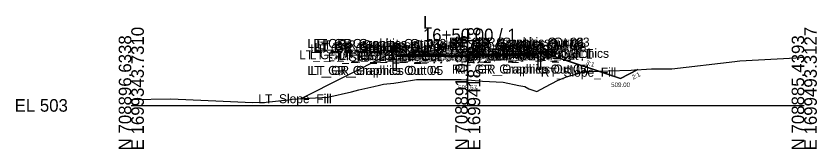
# Model space of a CAD drawing. Extents: x -63 to 1153, y -24 to 9522.
# Drawn here: x -25.7 to 152.8, y 7990.3 to 8019.9 of the extents above; entities that cross this region are included whole.
import ezdxf

# ---------------------------------------------------------------- set-up
doc = ezdxf.new("R2010")
doc.units = 0
for name, color, linetype in [('Default', 7, 'Continuous'), ('Exist Cross Section Cell', 7, 'Continuous'), ('Exist XS Center Line Elevation Label', 7, 'Continuous'), ('Exist XS Ground Line', 7, 'Continuous'), ('Prop CMT DNC', 7, 'Continuous'), ('Prop CMT Guardrail Graphics', 7, 'Continuous'), ('Prop CMT Pvmt Course 1', 7, 'Continuous'), ('Prop CMT Pvmt Course 2', 7, 'Continuous'), ('Prop CMT Pvmt Surface', 7, 'Continuous'), ('Prop CMT Pvmt Surface Overlay', 7, 'Continuous'), ('Prop CMT Pvmt Surface Shoulder', 7, 'Continuous'), ('Prop CMT Shld Paved Course 1', 7, 'Continuous'), ('Prop CMT Shld Paved Course 2', 7, 'Continuous'), ('Prop CMT Slope Grass', 7, 'Continuous'), ('Prop CMT Subgrade Earthwork', 7, 'Continuous'), ('Prop XS Ditch Standard Text', 7, 'Continuous'), ('Prop XS Earthwork Shape', 7, 'Continuous'), ('Prop XS EOT Tick Mark', 7, 'Continuous'), ('Prop XS SE Text', 7, 'Continuous'), ('Prop XS Side Slope Text', 7, 'Continuous')]:
    doc.layers.add(name, color=color, linetype=linetype)

msp = doc.modelspace()

# ---------------------------------------------------------------- linework, layer by layer
at = {"layer": 'Exist Cross Section Cell'}
for p, q in [((75, 8000), (75, 8017.09)), ((0, 8000), (75, 8000)), ((75, 8000), (150, 8000))]:
    msp.add_line(p, q, dxfattribs=at)
at = {"layer": 'Exist XS Ground Line'}
msp.add_lwpolyline([(0, 8001.3), (8.8, 8001.47), (20.45, 8000.98), (27.03, 8000.65), (30.06, 8000.69), (34.91, 8001.22), (35.88, 8001.36), (39.71, 8001.62), (43.79, 8001.8), (49.1, 8002.99), (50.72, 8003.47), (54.04, 8004.24), (55.31, 8004.54), (55.91, 8004.66), (56.23, 8004.7), (58.53, 8004.98), (59.96, 8005.18), (63.61, 8005.76), (68.55, 8005.77), (73.5, 8005.78), (75, 8005.67), (78.32, 8005.42), (82.88, 8005.17), (86.41, 8004.4), (87.72, 8004.22), (88.59, 8003.7), (90.41, 8003.11), (92.34, 8004.17), (95, 8005.51), (96.99, 8006.38), (100.4, 8007.3), (101.59, 8007.52), (106.3, 8007.67), (111.43, 8007.88), (115.95, 8008.14), (120.51, 8008.15), (134.52, 8009.8), (135.08, 8009.84), (135.66, 8009.89), (148.16, 8010.6), (150, 8010.77)], dxfattribs=at)
at = {"layer": 'Prop CMT Guardrail Graphics'}
for points in [[(58.37, 8007.79), (58.37, 8013.79)], [(58.37, 8013.79), (59.71, 8013.79), (59.98, 8013.5)], [(59.98, 8012.92), (59.71, 8012.63), (59.04, 8012.63)], [(59.04, 8012.63), (59.04, 8007.79)], [(59.98, 8013.5), (59.71, 8013.21)], [(59.71, 8013.21), (59.98, 8012.92)], [(91.28, 8014.09), (89.95, 8014.09), (89.68, 8013.8)], [(89.68, 8013.8), (89.95, 8013.51)], [(89.95, 8013.51), (89.68, 8013.22)], [(89.68, 8013.22), (89.95, 8012.93), (90.61, 8012.93)], [(90.61, 8012.93), (90.61, 8008.09)], [(91.28, 8008.09), (91.28, 8014.09)], [(59.04, 8007.79), (58.37, 8007.79)], [(90.61, 8008.09), (91.28, 8008.09)]]:
    msp.add_lwpolyline(points, dxfattribs=at)
at = {"layer": 'Prop CMT Pvmt Course 1'}
for points in [[(75, 8011.45), (65, 8011.35)], [(65, 8011.35), (65, 8011.1)], [(65, 8011.1), (75, 8011.2)], [(75, 8011.45), (85, 8011.55)], [(75, 8011.33), (75, 8011.45)], [(75, 8011.33), (75, 8011.45)], [(75, 8011.2), (75, 8011.33), (75, 8011.33)], [(75, 8011.2), (75, 8011.33), (75, 8011.33)], [(85, 8011.3), (75, 8011.2)], [(85, 8011.55), (85, 8011.3)]]:
    msp.add_lwpolyline(points, dxfattribs=at)
at = {"layer": 'Prop CMT Pvmt Course 2'}
for points in [[(75, 8011.2), (65, 8011.1)], [(65, 8011.1), (65, 8010.85)], [(65, 8010.85), (75, 8010.95)], [(75, 8011.2), (85, 8011.3)], [(75, 8010.95), (75, 8011.2)], [(75, 8010.95), (75, 8011.2)], [(85, 8011.05), (75, 8010.95)], [(85, 8011.3), (85, 8011.05)]]:
    msp.add_lwpolyline(points, dxfattribs=at)
at = {"layer": 'Prop CMT Pvmt Surface'}
for points in [[(75, 8011.45), (65, 8011.35)], [(75, 8011.45), (85, 8011.55)]]:
    msp.add_lwpolyline(points, dxfattribs=at)
at = {"layer": 'Prop CMT Pvmt Surface Overlay'}
for points in [[(75, 8011.45), (65, 8011.35)], [(75, 8011.45), (85, 8011.55)]]:
    msp.add_lwpolyline(points, dxfattribs=at)
at = {"layer": 'Prop CMT Pvmt Surface Shoulder'}
for points in [[(65, 8011.35), (60.16, 8011.31)], [(85, 8011.55), (89.58, 8011.6)]]:
    msp.add_lwpolyline(points, dxfattribs=at)
at = {"layer": 'Prop CMT Shld Paved Course 1'}
for points in [[(65, 8011.35), (60.16, 8011.31), (59.91, 8011.05)], [(59.91, 8011.05), (65, 8011.1)], [(65, 8011.1), (65, 8011.35)], [(85, 8011.55), (89.58, 8011.6), (89.82, 8011.35)], [(85, 8011.3), (85, 8011.55)], [(89.82, 8011.35), (85, 8011.3)]]:
    msp.add_lwpolyline(points, dxfattribs=at)
at = {"layer": 'Prop CMT Shld Paved Course 2'}
for points in [[(59.91, 8011.05), (59.66, 8010.8)], [(59.66, 8010.8), (65, 8010.85)], [(65, 8011.1), (59.91, 8011.05)], [(59.91, 8011.05), (59.91, 8011.05)], [(65, 8010.85), (65, 8011.1)], [(85, 8011.3), (89.82, 8011.35)], [(85, 8011.05), (85, 8011.3)], [(90.07, 8011.1), (85, 8011.05)], [(89.82, 8011.35), (89.82, 8011.35)], [(89.82, 8011.35), (90.07, 8011.1)]]:
    msp.add_lwpolyline(points, dxfattribs=at)
at = {"layer": 'Prop CMT Slope Grass'}
for p, q in [((92.68, 8011.44), (109.01, 8006)), ((109.01, 8006), (112.94, 8007.96))]:
    msp.add_line(p, q, dxfattribs=at)
for points in [[(56.98, 8011.08), (37.79, 8001.49)], [(59.98, 8011.29), (56.98, 8011.08)], [(60.16, 8011.31), (59.98, 8011.29)], [(89.58, 8011.6), (89.68, 8011.59)], [(89.68, 8011.59), (92.68, 8011.44)]]:
    msp.add_lwpolyline(points, dxfattribs=at)
at = {"layer": 'Prop CMT Subgrade Earthwork'}
for points in [[(59.66, 8010.8), (59.22, 8011.24)], [(65, 8010.85), (59.66, 8010.8)], [(75, 8010.95), (65, 8010.85)], [(75, 8010.95), (85, 8011.05)], [(85, 8011.05), (90.07, 8011.1)], [(90.07, 8011.1), (90.52, 8011.55)]]:
    msp.add_lwpolyline(points, dxfattribs=at)
at = {"layer": 'Prop XS Earthwork Shape'}
for points in [[(56.98, 8011.08), (37.79, 8001.49), (39.71, 8001.62), (43.79, 8001.8), (49.1, 8002.99), (50.72, 8003.47), (54.04, 8004.24), (55.31, 8004.54), (55.91, 8004.66), (56.23, 8004.7), (58.53, 8004.98), (59.96, 8005.18), (63.61, 8005.76), (68.55, 8005.77), (73.5, 8005.78), (75, 8005.67), (78.32, 8005.42), (82.88, 8005.17), (86.41, 8004.4), (87.72, 8004.22), (88.59, 8003.7), (90.41, 8003.11), (92.34, 8004.17), (95, 8005.51), (96.99, 8006.38), (100.4, 8007.3), (101.59, 8007.52), (104.21, 8007.6), (92.68, 8011.44), (90.52, 8011.55), (90.07, 8011.1), (85, 8011.05), (75, 8010.95), (65, 8010.85), (59.66, 8010.8), (59.22, 8011.24)], [(106.3, 8007.67), (111.43, 8007.88), (112.94, 8007.96), (109.01, 8006), (104.21, 8007.6)]]:
    msp.add_lwpolyline(points, close=True, dxfattribs=at)
at = {"layer": 'Prop XS EOT Tick Mark'}
for points in [[(85, 8011.55), (85, 8012.55)], [(65, 8011.35), (65, 8012.35)]]:
    msp.add_lwpolyline(points, dxfattribs=at)

# ---------------------------------------------------------------- texts
at = {"layer": 'Default'}
msp.add_text('-', height=0.0001, dxfattribs=at).set_placement((0, 8000))
at = {"layer": 'Exist Cross Section Cell'}
for s, p in [('L', (65, 8017.09)), ('16+50.00 / 1', (65, 8014.29)), ('EL 503', (-26, 7998.6))]:
    msp.add_text(s, height=2.8, dxfattribs=at).set_placement(p)
for s, p in [('E 1699343.7310', (2.8, 7990)), ('E 1699418.5218', (77.8, 7990)), ('E 1699493.3127', (152.8, 7990)), ('N 708896.6338', (0, 7990)), ('N 708891.0366', (75, 7990)), ('N 708885.4393', (150, 7990))]:
    msp.add_text(s, height=2.8, rotation=90, dxfattribs=at).set_placement(p)
at = {"layer": 'Exist XS Center Line Elevation Label'}
msp.add_text('508.67', height=1, dxfattribs=at).set_placement((72.85, 8003.49))
at = {"layer": 'Prop CMT DNC'}
for s, p in [('LT_GR_Graphics Out 03', (39.27, 8012.79)), ('LT_GR_Graphics Out 02', (40.6, 8012.79)), ('LT_GR_Graphics Out 01', (41.44, 8012.5)), ('RT_GR_Graphics Out 02', (70.8, 8013.09)), ('RT_GR_Graphics Out 09', (70.8, 8012.51)), ('RT_GR_Graphics Out 01', (71.09, 8012.8)), ('RT_GR_Graphics Out 03', (72.13, 8013.09)), ('LT_GR_Graphics Out 06', (39.89, 8011.63)), ('LT_GR_Graphics Out 09', (40.6, 8012.21)), ('LT_GR_Graphics Out 07', (40.6, 8011.63)), ('LT_GR_Graphics Out 08', (40.87, 8011.92)), ('LT_TM_OEOT', (55.94, 8011.35)), ('RT_GS_OS_GR_Face_Graphics', (67.09, 8010.59)), ('RT_GR_Graphics Out 08', (70.53, 8012.22)), ('RT_GR_Graphics Out 07', (70.8, 8011.93)), ('RT_Sub_Trench_Out_DLT', (71.04, 8010.55)), ('RT_GR_Graphics Out 06', (71.42, 8011.93)), ('RT_PV1_OEOT', (75.69, 8010.55)), ('RT_TM_OEOT', (75.9, 8011.55)), ('RT_PS1_OEOP', (80.33, 8010.6)), ('LT_GS_OS_GR_Face_Graphics', (37.43, 8010.29)), ('LT_Sub_Trench_Out_DLT', (39.78, 8010.24)), ('LT_Sub_Trench_Out', (43.86, 8009.8)), ('LT_PS2_Shelf_Out', (45.89, 8010.05)), ('LT_GS_OS_CTL', (46.35, 8010.08)), ('LT_PS2_OEOP', (50.15, 8010.05)), ('LT_PS1_OEOP', (50.96, 8010.31)), ('LT_Sub_OEOT', (55.08, 8009.85)), ('LT_PV2_OEOT', (55.17, 8010.1)), ('LT_PV1_OEOT', (55.74, 8010.35)), ('RT_PV1_OEEOP_W', (62.94, 8010.33)), ('LT_PV1_OEEOP_W', (62.98, 8010.33)), ('RT_Sub_OEEOP', (64.17, 8009.95)), ('LT_Sub_OEEOP', (64.21, 8009.95)), ('RT_PV2_OEEOP', (64.26, 8010.2)), ('LT_PV2_OEEOP', (64.31, 8010.2)), ('PV1_PGL_W', (67.58, 8010.33)), ('PV1_PGL', (69.47, 8010.45)), ('RT_Sub_Trench_Out', (74.23, 8010.1)), ('RT_Sub_OEOT', (75.03, 8010.05)), ('RT_PV2_OEOT', (75.13, 8010.3)), ('RT_PS2_Shelf_Out', (75.76, 8010.35)), ('RT_PS2_OEOP', (80.01, 8010.35)), ('RT_GS_OS_CTL', (82, 8010.44)), ('RT_GR_Graphics Out 05', (71.46, 8007.09)), ('RT_GR_Graphics Out 04', (72.13, 8007.09)), ('LT_GR_Graphics Out 04', (39.27, 8006.79)), ('LT_GR_Graphics Out 05', (39.94, 8006.79)), ('RT_Slope_Fill', (91.28, 8006.38)), ('LT_Slope_Fill', (28.31, 8000.49))]:
    msp.add_text(s, height=2, dxfattribs=at).set_placement(p)
at = {"layer": 'Prop XS Ditch Standard Text'}
msp.add_text('509.00', height=1, dxfattribs=at).set_placement((106.96, 8004.09))
at = {"layer": 'Prop XS SE Text'}
for p in [(68.36, 8012.39), (78.36, 8012.49)]:
    msp.add_text('0.010', height=1, rotation=0.5729, dxfattribs=at).set_placement(p)
at = {"layer": 'Prop XS Side Slope Text'}
for s, rotation, p in [('3:1', 341.5651, (101.25, 8009.14)), ('2:1', 26.5651, (46.34, 8006.6)), ('2:1', 26.5651, (111.87, 8005.72))]:
    msp.add_text(s, height=1, rotation=rotation, dxfattribs=at).set_placement(p)

doc.saveas('drawing.dxf')
